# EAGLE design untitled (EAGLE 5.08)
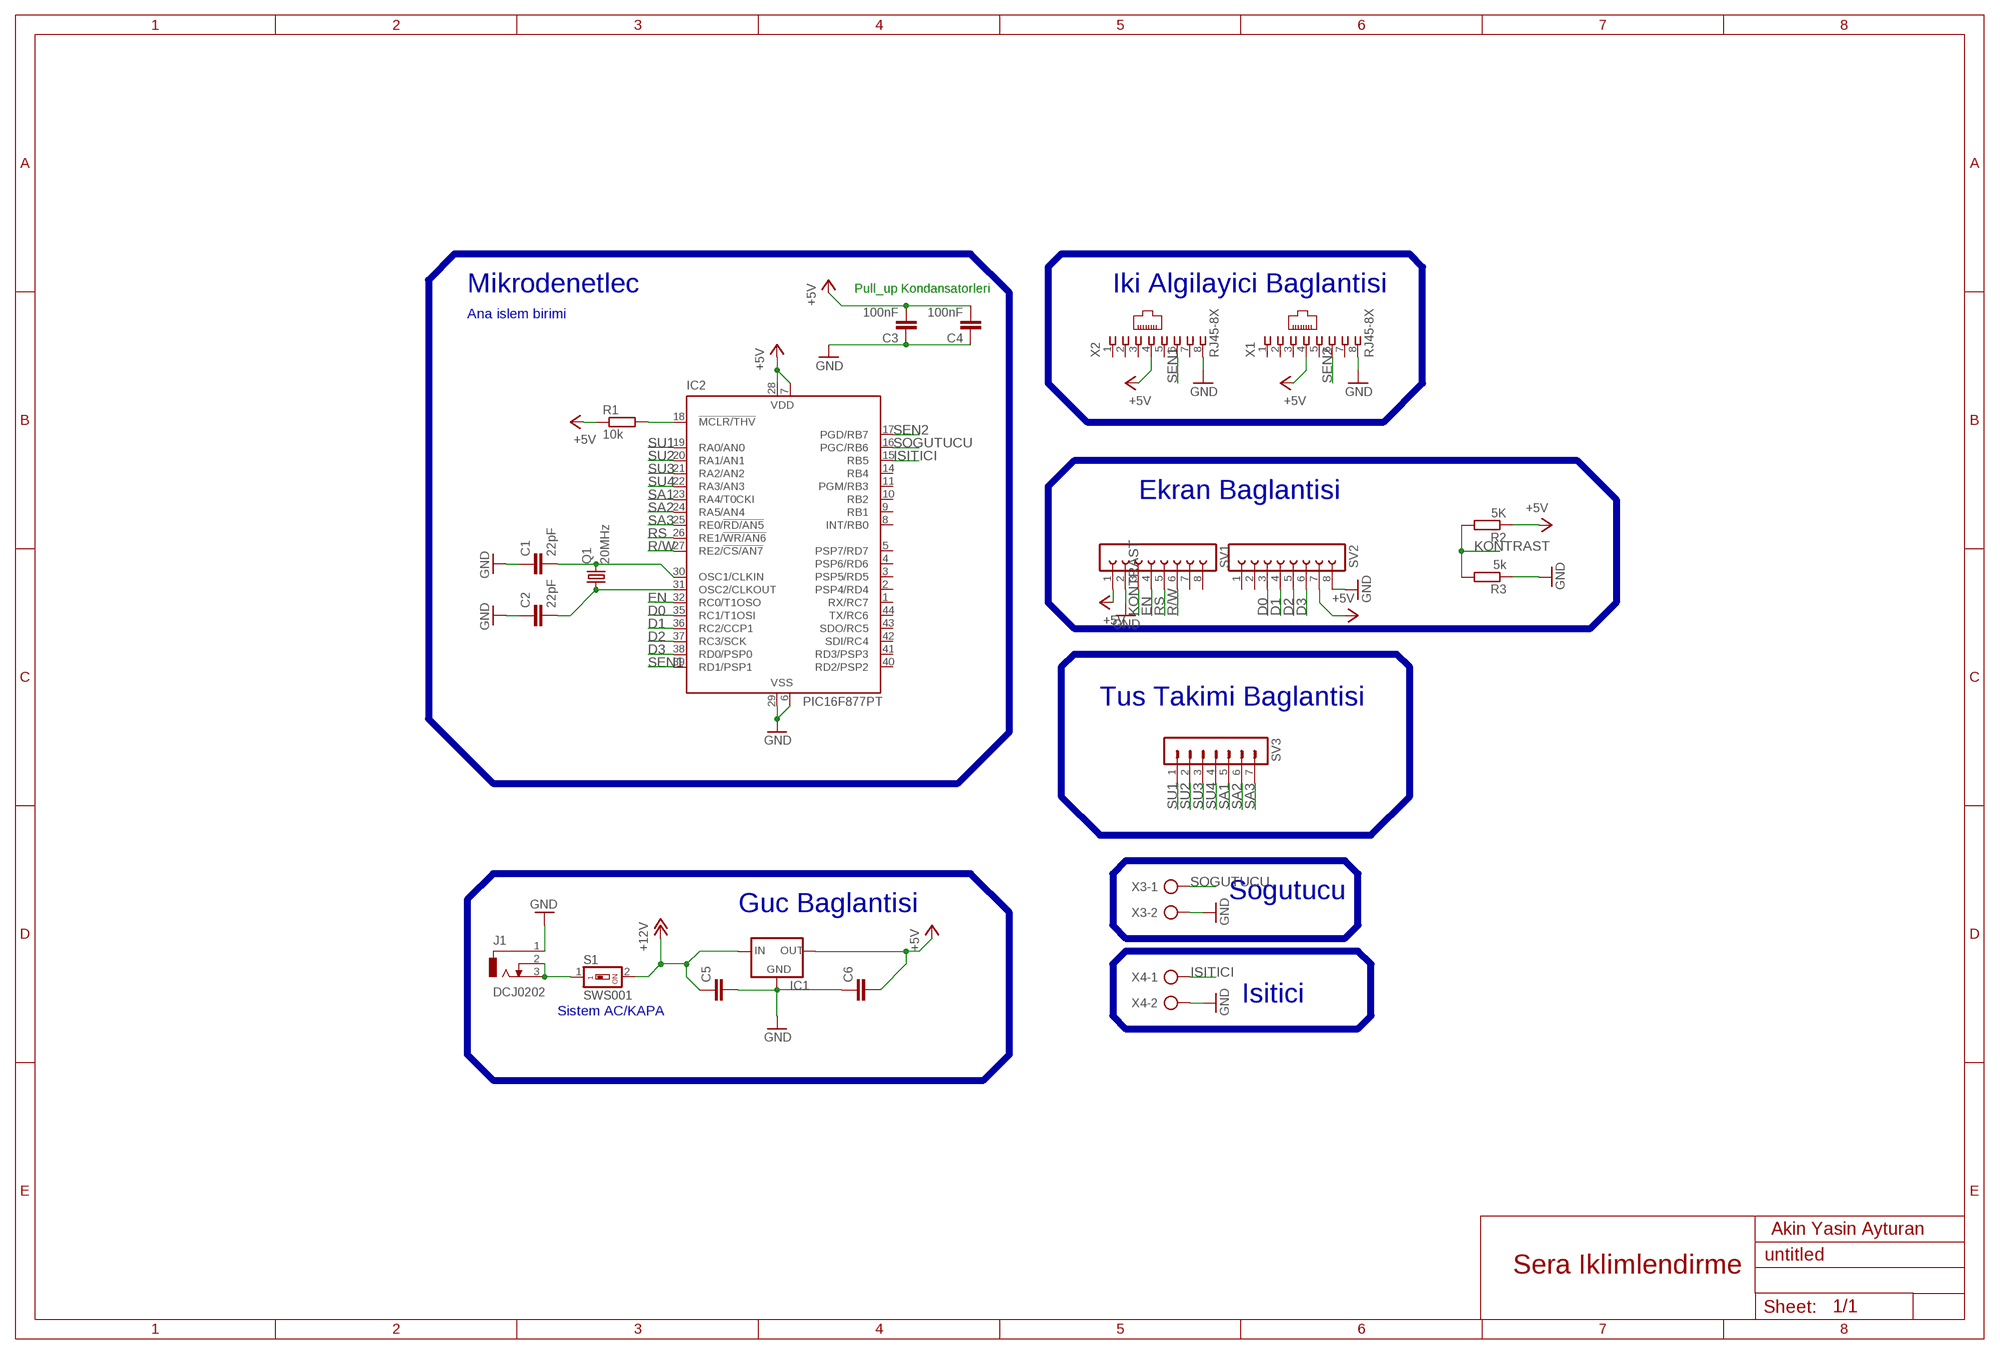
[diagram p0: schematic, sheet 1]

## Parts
C1  22pF  C-EUC0402  [C0402]
C2  22pF  C-EUC0402  [C0402]
C3  100nF  C-EUC1206  [C1206]
C4  100nF  C-EUC1206  [C1206]
C5  C-EU050-045X075  [C050-045X075]
C6  C-EU050-045X075  [C050-045X075]
IC1  78LXX  [78LXX]
IC2  PIC16F877PT  [TQFP44]
J1  DCJ0202  [DCJ0202]
Q1  20MHz  CRYSTALSM49  [SM49]
R1  10k  R-EU_M1206  [M1206]
R2  5K  R-EU_M1206  [M1206]
R3  5k  R-EU_M1206  [M1206]
S1  SWS001  [SMS-001]
SV1  FE08-1  [FE08]
SV2  FE08-1  [FE08]
SV3  MA07-1  [MA07-1]
X1  RJ45-8X  [RJ45-NO-SHIELD]
X2  RJ45-8X  [RJ45-NO-SHIELD]
X3  AK300/2  [AK300/2]
X4  AK300/2  [AK300/2]

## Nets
+5V: C3.2 C4.2 C6.2 IC1.OUT IC2.7(VDD) IC2.28(VDD) R1.1 R2.1 SV1.1 SV2.7 X1.4 X2.4
+12V: C5.1 IC1.IN S1.2
D0: IC2.35(RC1/T1OSI) SV2.3
D1: IC2.36(RC2/CCP1) SV2.4
D2: IC2.37(RC3/SCK) SV2.5
D3: IC2.38(RD0/PSP0) SV2.6
EN: IC2.32(RC0/T1OSO) SV1.4
GND: C1.1 C2.1 C3.1 C4.1 C5.2 C6.1 IC1.GND IC2.6(VSS) IC2.29(VSS) J1.1 R3.1 SV1.2 SV2.8 X1.8 X2.8 X3.2 X4.2
ISITICI: IC2.15(RB5) X4.1
KONTRAST: R2.2 R3.2 SV1.3
N$1: IC2.18(!MCLR/THV) R1.2
N$2: C1.2 IC2.30(OSC1/CLKIN) Q1.2
N$3: C2.2 IC2.31(OSC2/CLKOUT) Q1.1
N$4: J1.2 J1.3 S1.1
R/W: IC2.27(RE2/!CS/AN7) SV1.6
RS: IC2.26(RE1/!WR/AN6) SV1.5
SA1: IC2.23(RA4/T0CKI) SV3.5
SA2: IC2.24(RA5/AN4) SV3.6
SA3: IC2.25(RE0/!RD/AN5) SV3.7
SEN1: IC2.39(RD1/PSP1) X2.6
SEN2: IC2.17(PGD/RB7) X1.6
SOGUTUCU: IC2.16(PGC/RB6) X3.1
SU1: IC2.19(RA0/AN0) SV3.1
SU2: IC2.20(RA1/AN1) SV3.2
SU3: IC2.21(RA2/AN2) SV3.3
SU4: IC2.22(RA3/AN3) SV3.4
Unconnected: IC2.1(RX/RC7) IC2.2(PSP4/RD4) IC2.3(PSP5/RD5) IC2.4(PSP6/RD6) IC2.5(PSP7/RD7) IC2.8(INT/RB0) IC2.9(RB1) IC2.10(RB2) IC2.11(PGM/RB3) IC2.14(RB4) IC2.40(RD2/PSP2) IC2.41(RD3/PSP3) IC2.42(SDI/RC4) IC2.43(SDO/RC5) IC2.44(TX/RC6) SV1.7 SV1.8 SV2.1 SV2.2 X1.1 X1.2 X1.3 X1.5 X1.7 X2.1 X2.2 X2.3 X2.5 X2.7

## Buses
B$2
B$3
B$4
B$5
B$6
B$7
B$1

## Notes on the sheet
- Mikrodenetlec | Pull_up Kondansatorleri | Iki Algilayici Baglantisi
- Ana islem birimi
- Ekran Baglantisi
- Tus Takimi Baglantisi
- Sogutucu
- Guc Baglantisi
- Isitici
- Sistem AC/KAPA
- Akin Yasin Ayturan
- Sera Iklimlendirme

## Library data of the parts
C1-C6 = resistor:C-EU: CAPACITOR, European symbol
IC1 = v-reg:78LXX: VOLTAGE REGULATOR
IC2 = microchip:PIC16F87*: MICROCONTROLLER
J1 = con-jack:DCJ0202: DC POWER JACK Source: DCJ0202.pdf
Q1 = crystal:CRYSTAL: CRYSTAL
R1-R3 = resistor:R-EU_: RESISTOR, European symbol
S1 = smd-special:SWS001: SMD Dip Switch 1 pol.
SV1 SV2 = con-lsta:FE08-1: FEMALE HEADER
SV3 = con-lstb:MA07-1: PIN HEADER
X1 X2 = con-tycoelectronics:RJ45: CORCOM Modular RJ Jacks No Shield Source: www.tycoelectronics.com .. ENG_DS_1654001_1099_RJ_L_0507.pdf
X3 X4 = con-ptr500:AK300/2: CONNECTOR

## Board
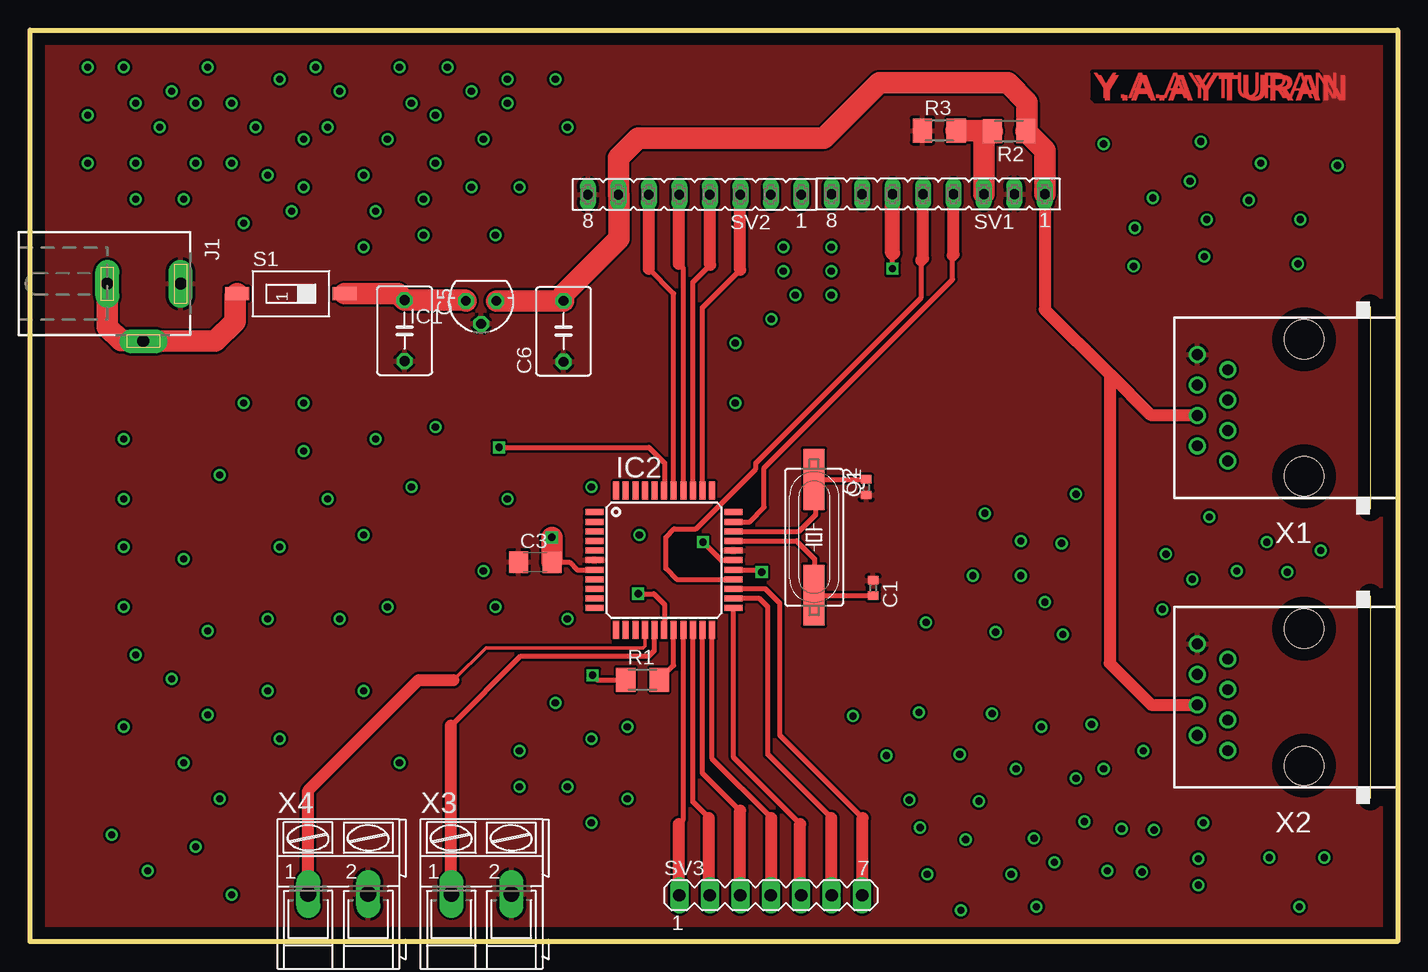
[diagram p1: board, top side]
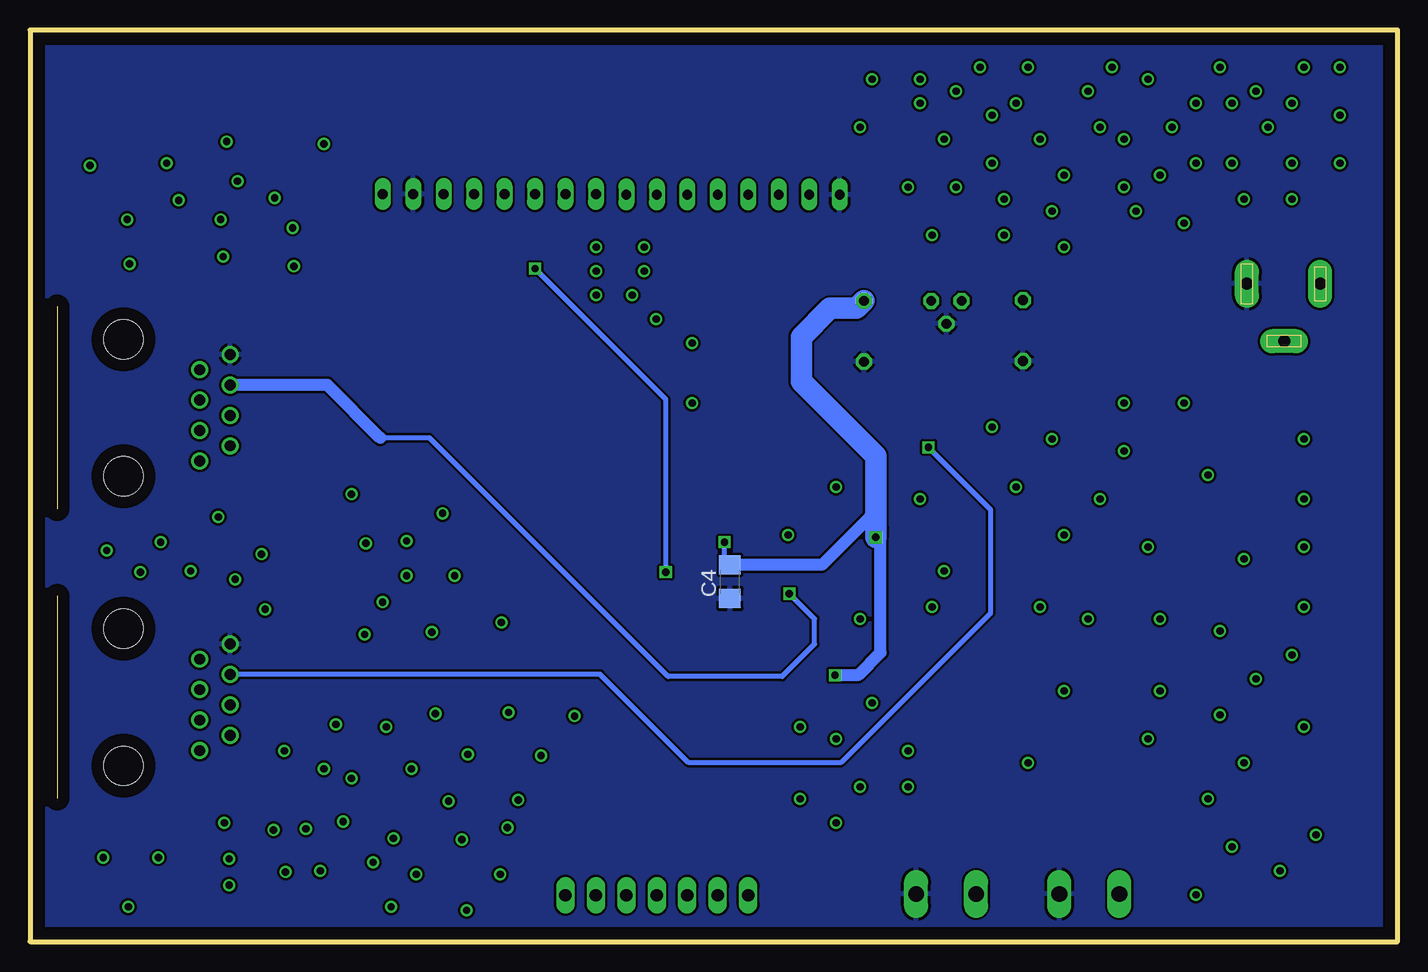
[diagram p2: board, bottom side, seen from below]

Size 114 x 76 mm. Coordinates in mm from the lower left corner, seen from the top.
Outline: 0,0 0,76 114,76 114,0 0,0
Copper layers (1*16): Top 0.035mm / dielectric 1.5mm / Bottom 0.035mm
Design rules "default": minimum track width 10mil, minimum drill 24mil, track to track 8mil, track to pad 8mil, pad to pad 8mil, via to via 8mil, smd to smd 8mil, copper to edge 40mil, drill to drill 8mil, minimum pad ring 10mil, minimum via ring 8mil, stop-mask expansion 4mil, vias tented up to drill 0mil, thermal gap 10mil

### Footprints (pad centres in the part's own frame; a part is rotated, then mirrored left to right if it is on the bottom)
C0402 = smd 0.7 x 0.9: 1 -0.65,0; 2 0.65,0
C1206 = smd 1.6 x 1.8: 1 -1.4,0; 2 1.4,0
C050-045X075 = drill 0.813 octagon: 1 -2.54,0; 2 2.54,0
78LXX = drill 0.813 octagon: GND 0,1.905; IN 1.27,0; OUT -1.27,0
TQFP44 = smd 1.5 x 0.5: 1 -5.8,4; 2 -5.8,3.2; 3 -5.8,2.4; 4 -5.8,1.6; 5 -5.8,0.8; 6 -5.8,0; 7 -5.8,-0.8; 8 -5.8,-1.6; 9 -5.8,-2.4; 10 -5.8,-3.2; 11 -5.8,-4; 23 5.8,-4; 24 5.8,-3.2; 25 5.8,-2.4; 26 5.8,-1.6; 27 5.8,-0.8; 28 5.8,0; 29 5.8,0.8; 30 5.8,1.6; 31 5.8,2.4; 32 5.8,3.2; 33 5.8,4 | smd 0.5 x 1.5: 12 -4,-5.8; 13 -3.2,-5.8; 14 -2.4,-5.8; 15 -1.6,-5.8; 16 -0.8,-5.8; 17 0,-5.8; 18 0.8,-5.8; 19 1.6,-5.8; 20 2.4,-5.8; 21 3.2,-5.8; 22 4,-5.8; 34 4,5.8; 35 3.2,5.8; 36 2.4,5.8; 37 1.6,5.8; 38 0.8,5.8; 39 0,5.8; 40 -0.8,5.8; 41 -1.6,5.8; 42 -2.4,5.8; 43 -3.2,5.8; 44 -4,5.8
DCJ0202 = drill 1 pad 2 long: 1 0,3.1; 2 4.8,0; 3 0,-3
SM49 = smd 5.08 x 1.778: 1 -4.826,0; 2 4.826,0
M1206 = smd 1.6 x 2: 1 -1.4,0; 2 1.4,0
SMS-001 = smd 1.092 x 2.007: 1 0,-4.496; 2 0,4.496
FE08 = drill 0.813 long: 1 -8.89,0; 2 -6.35,0; 3 -3.81,0; 4 -1.27,0; 5 1.27,0; 6 3.81,0; 7 6.35,0; 8 8.89,0
MA07-1 = drill 1.016 long: 1 -7.62,0; 2 -5.08,0; 3 -2.54,0; 4 0,0; 5 2.54,0; 6 5.08,0; 7 7.62,0
RJ45-NO-SHIELD = drill 0.9 pad 1.4 round: 1 -4.445,6.35; 2 -3.175,8.89; 3 -1.905,6.35; 4 -0.635,8.89; 5 0.635,6.35; 6 1.905,8.89; 7 3.175,6.35; 8 4.445,8.89 | hole 3.251: -5.715,0; 5.715,0
AK300/2 = drill 1.321 long: 1 -2.515,0; 2 2.489,0

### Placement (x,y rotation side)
C1  70.29,29.47 270 top
C2  69.71,37.88 90 top
C3  42.12,31.64 0 top
C4  55.66,30 90 bottom
C5  31.22,50.93 270 top
C6  44.48,50.88 90 top
IC1  37.61,53.41 180 top
IC2  52.86,31.8 0 top
J1  9.45,54.85 270 top
Q1  65.36,33.7 270 top
R1  51.06,21.82 0 top
R2  81.62,67.58 180 top
R3  75.8,67.62 0 top
S1  21.75,54.01 270 top
SV1  75.71,62.32 180 top
SV2  55.4,62.28 180 top
SV3  61.75,3.86 0 top
X1  106.2,44.5 90 top
X2  106.2,20.37 90 top
X3  37.64,3.96 0 top
X4  25.71,3.96 0 top

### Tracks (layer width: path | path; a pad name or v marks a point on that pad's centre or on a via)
+5V  (via drill 0.6)
  Top 0.406: C3.2 44.96,31.64 45.6,31 IC2.7 | R1.1 47.28,21.82 v46.9,22.2 | IC2.28 57.6,31.8 v56.1,33.3
  Top 1.016: SV1.1 84.6,52.7 90,47.3 | 90,47.3 93.4,43.9 97.28,43.9 X1.4 | X2.4 93.47,19.73 90,23.2 90,47.3
  Top 1.778: IC1.OUT C6.2 44.48,53.98 49.1,58.6 49.1,62.23 SV2.7 49.05,65.35 50.7,67 66.2,67 70.8,71.6 81.5,71.6 83.1,70 83.1,67.66 R2.1 84.6,66 SV1.1 | C3.2 43.52,33.68 v43.5,33.7
  Bottom 0.406: v56.1,33.3 56.1,31.84 C4.2
  Bottom 1.016: v46.9,22.2 45,22.2 43.1,24.1 43.1,34.2 43.5,34.6 | C4.2 48,31.4 44,35.4 43.6,35.4 43.5,35.5
  Bottom 1.778: v43.5,33.7 43.5,34.6 43.5,35.5 43.5,40.5 49.7,46.7 49.7,50.4 47.3,52.8 45.1,52.8 C6.2
+12V
  Top 1.778: S1.2 30.68,54.01 C5.1 36.28,53.47 IC1.IN
D0
  Top 0.406: IC2.35 56.06,52.86 59.2,56
  Top 1.016: 59.2,56 SV2.3
D1
  Top 0.406: IC2.36 55.26,54.96 56.7,56.4
  Top 1.016: 56.7,56.4 56.7,62.25 SV2.4
D2
  Top 0.406: IC2.37 54.46,56.14 54.1,56.5
  Top 1.016: 54.1,56.5 54.1,62.25 SV2.5
D3
  Top 0.406: IC2.38 53.66,54.04 51.6,56.1
  Top 1.016: 51.6,56.1 SV2.6
EN
  Top 0.406: 76.9,57.2 76.9,55.2 61.2,39.5 61.2,36.2 60,35 IC2.32
  Top 1.016: SV1.4 76.98,57.28 76.9,57.2
GND
  pour Top: 0.8,61.9 0.8,0.9 112.8,0.9 112.8,74.9 0.8,74.9
  pour Bottom: 0.8,74.9 0.8,0.9 112.8,0.9 112.8,74.9
ISITICI
  Top 0.305: IC2.15 51.26,24.66 51.1,24.5 38,24.5 35.3,21.8
  Top 1.016: 35.3,21.8 32.4,21.8 23.2,12.6 X4.1
KONTRAST
  Top 1.778: SV1.3 79.52,66.88 R2.2 80.18,67.62 R3.2
N$1
  Top 0.406: IC2.18 53.66,23.02 R1.2
N$2
  Top 0.406: IC2.30 63.9,33.4 65.4,31.9 65.4,28.91 Q1.2 70.24,28.87 C1.2
N$3
  Top 0.406: IC2.31 64.1,34.2 65.5,35.6 65.5,38.39 Q1.1 C2.2
N$4
  Top 1.778: J1.3 6.45,51.25 7.6,50.1 9.4,50.1 J1.2 15.45,50.05 17.1,51.7 17.1,53.86 S1.1
N$5  (via drill 0.6)
  other vias: 7.8,41.9
N$6  (via drill 0.6)
  other vias: 7.8,36.9
N$7  (via drill 0.6)
  other vias: 7.8,32.9
N$8  (via drill 0.6)
  other vias: 7.8,27.9
N$9  (via drill 0.6)
  other vias: 8.8,23.9
N$10  (via drill 0.6)
  other vias: 7.8,17.9
N$11  (via drill 0.6)
  other vias: 6.8,8.9
N$12  (via drill 0.6)
  other vias: 12.8,14.9
N$13  (via drill 0.6)
  other vias: 11.8,21.9
N$14  (via drill 0.6)
  other vias: 19.8,26.9
N$15  (via drill 0.6)
  other vias: 12.8,31.9
N$16  (via drill 0.6)
  other vias: 15.8,38.9
N$17  (via drill 0.6)
  other vias: 24.8,36.9
N$18  (via drill 0.6)
  other vias: 20.8,32.9
N$19  (via drill 0.6)
  other vias: 25.8,26.9
N$20  (via drill 0.6)
  other vias: 19.8,20.9
N$21  (via drill 0.6)
  other vias: 27.8,20.9
N$22  (via drill 0.6)
  other vias: 14.8,25.9
N$23  (via drill 0.6)
  other vias: 22.8,44.9
N$24  (via drill 0.6)
  other vias: 17.8,44.9
N$25  (via drill 0.6)
  other vias: 22.8,40.9
N$26  (via drill 0.6)
  other vias: 33.8,42.9
N$27  (via drill 0.6)
  other vias: 28.8,41.9
N$28  (via drill 0.6)
  other vias: 27.8,33.9
N$29  (via drill 0.6)
  other vias: 29.8,27.9
N$30  (via drill 0.6)
  other vias: 31.8,37.9
N$31  (via drill 0.6)
  other vias: 39.8,36.9
N$32  (via drill 0.6)
  other vias: 37.8,30.9
N$33  (via drill 0.6)
  other vias: 38.8,27.9
N$34  (via drill 0.6)
  other vias: 46.8,37.9
N$35  (via drill 0.6)
  other vias: 44.8,26.9
N$36  (via drill 0.6)
  other vias: 50.8,33.9
N$37  (via drill 0.6)
  other vias: 43.8,19.9
N$38  (via drill 0.6)
  other vias: 49.8,17.9
N$39  (via drill 0.6)
  other vias: 46.8,16.9
N$40  (via drill 0.6)
  other vias: 40.8,15.9
N$41  (via drill 0.6)
  other vias: 49.8,11.9
N$42  (via drill 0.6)
  other vias: 40.8,12.9
N$43  (via drill 0.6)
  other vias: 46.8,9.9
N$44  (via drill 0.6)
  other vias: 44.8,12.9
N$45  (via drill 0.6)
  other vias: 30.8,14.9
N$46  (via drill 0.6)
  other vias: 15.8,11.9
N$47  (via drill 0.6)
  other vias: 13.8,7.9
N$48  (via drill 0.6)
  other vias: 16.8,3.9
N$49  (via drill 0.6)
  other vias: 9.8,5.9
N$50  (via drill 0.6)
  other vias: 20.8,16.9
N$51  (via drill 0.6)
  other vias: 14.8,18.9
N$52  (via drill 0.6)
  other vias: 4.8,72.9
N$53  (via drill 0.6)
  other vias: 4.8,68.9
N$54  (via drill 0.6)
  other vias: 4.8,64.9
N$55  (via drill 0.6)
  other vias: 8.8,64.9
N$56  (via drill 0.6)
  other vias: 10.8,67.9
N$57  (via drill 0.6)
  other vias: 11.8,70.9
N$58  (via drill 0.6)
  other vias: 7.8,72.9
N$59  (via drill 0.6)
  other vias: 8.8,69.9
N$60  (via drill 0.6)
  other vias: 20.8,71.9
N$61  (via drill 0.6)
  other vias: 18.8,67.9
N$62  (via drill 0.6)
  other vias: 16.8,69.9
N$63  (via drill 0.6)
  other vias: 14.8,72.9
N$64  (via drill 0.6)
  other vias: 16.8,64.9
N$65  (via drill 0.6)
  other vias: 13.8,64.9
N$66  (via drill 0.6)
  other vias: 13.8,69.9
N$67  (via drill 0.6)
  other vias: 22.8,62.9
N$68  (via drill 0.6)
  other vias: 17.8,59.9
N$69  (via drill 0.6)
  other vias: 12.8,61.9
N$70  (via drill 0.6)
  other vias: 8.8,61.9
N$71  (via drill 0.6)
  other vias: 21.8,60.9
N$72  (via drill 0.6)
  other vias: 27.8,57.9
N$73  (via drill 0.6)
  other vias: 19.8,63.9
N$74  (via drill 0.6)
  other vias: 24.8,67.9
N$75  (via drill 0.6)
  other vias: 22.8,66.9
N$76  (via drill 0.6)
  other vias: 25.8,70.9
N$77  (via drill 0.6)
  other vias: 31.8,69.9
N$78  (via drill 0.6)
  other vias: 29.8,66.9
N$79  (via drill 0.6)
  other vias: 27.8,63.9
N$80  (via drill 0.6)
  other vias: 32.8,61.9
N$81  (via drill 0.6)
  other vias: 32.8,58.9
N$82  (via drill 0.6)
  other vias: 38.8,58.9
N$83  (via drill 0.6)
  other vias: 28.8,60.9
N$84  (via drill 0.6)
  other vias: 33.8,64.9
N$85  (via drill 0.6)
  other vias: 40.8,62.9
N$86  (via drill 0.6)
  other vias: 36.8,62.9
N$87  (via drill 0.6)
  other vias: 37.8,66.9
N$88  (via drill 0.6)
  other vias: 33.8,68.9
N$89  (via drill 0.6)
  other vias: 44.8,67.9
N$90  (via drill 0.6)
  other vias: 39.8,69.9
N$91  (via drill 0.6)
  other vias: 36.8,70.9
N$92  (via drill 0.6)
  other vias: 43.8,71.9
N$93  (via drill 0.6)
  other vias: 39.8,71.9
N$94  (via drill 0.6)
  other vias: 34.8,72.9
N$95  (via drill 0.6)
  other vias: 30.8,72.9
N$96  (via drill 0.6)
  other vias: 23.8,72.9
N$97  (via drill 0.6)
  other vias: 62.8,57.9
N$98  (via drill 0.6)
  other vias: 66.8,57.9
N$99  (via drill 0.6)
  other vias: 62.8,55.9
N$100  (via drill 0.6)
  other vias: 61.8,51.9
N$101  (via drill 0.6)
  other vias: 58.8,49.9
N$102  (via drill 0.6)
  other vias: 58.8,44.9
N$103  (via drill 0.6)
  other vias: 66.8,53.9
N$104  (via drill 0.6)
  other vias: 63.8,53.9
N$105  (via drill 0.6)
  other vias: 66.8,55.9
N$106  (via drill 0.6)
  other vias: 68.6,18.8
N$107  (via drill 0.6)
  other vias: 71.4,15.5
N$108  (via drill 0.6)
  other vias: 73.3,11.8
N$109  (via drill 0.6)
  other vias: 74.8,5.6
N$110  (via drill 0.6)
  other vias: 74.2,9.5
N$111  (via drill 0.6)
  other vias: 81.8,5.6
N$112  (via drill 0.6)
  other vias: 79.1,11.7
N$113  (via drill 0.6)
  other vias: 78,8.5
N$114  (via drill 0.6)
  other vias: 77.5,15.6
N$115  (via drill 0.6)
  other vias: 84.3,17.9
N$116  (via drill 0.6)
  other vias: 74.1,19.1
N$117  (via drill 0.6)
  other vias: 82.2,14.4
N$118  (via drill 0.6)
  other vias: 87.9,10
N$119  (via drill 0.6)
  other vias: 83.7,8.6
N$120  (via drill 0.6)
  other vias: 89.5,14.4
N$121  (via drill 0.6)
  other vias: 80.2,19
N$122  (via drill 0.6)
  other vias: 88.5,18.1
N$123  (via drill 0.6)
  other vias: 92.8,15.9
N$124  (via drill 0.6)
  other vias: 93.7,9.3
N$125  (via drill 0.6)
  other vias: 87.2,13.6
N$126  (via drill 0.6)
  other vias: 85.4,6.6
N$127  (via drill 0.6)
  other vias: 92.7,5.8
N$128  (via drill 0.6)
  other vias: 89.8,5.9
N$129  (via drill 0.6)
  other vias: 91,9.4
N$130  (via drill 0.6)
  other vias: 97.8,9.9
N$131  (via drill 0.6)
  other vias: 97.4,4.7
N$132  (via drill 0.6)
  other vias: 97.4,6.9
N$133  (via drill 0.6)
  other vias: 105.8,2.9
N$134  (via drill 0.6)
  other vias: 107.9,7
N$135  (via drill 0.6)
  other vias: 103.3,7
N$136  (via drill 0.6)
  other vias: 83.9,2.9
N$137  (via drill 0.6)
  other vias: 77.6,2.6
N$138  (via drill 0.6)
  other vias: 74.7,26.6
N$139  (via drill 0.6)
  other vias: 79.6,35.7
N$140  (via drill 0.6)
  other vias: 78.6,30.5
N$141  (via drill 0.6)
  other vias: 84.6,28.3
N$142  (via drill 0.6)
  other vias: 82.6,33.4
N$143  (via drill 0.6)
  other vias: 87.2,37.3
N$144  (via drill 0.6)
  other vias: 82.6,30.5
N$145  (via drill 0.6)
  other vias: 80.5,25.8
N$146  (via drill 0.6)
  other vias: 86,33.2
N$147  (via drill 0.6)
  other vias: 86.1,25.6
N$148  (via drill 0.6)
  other vias: 98.3,35.4
N$149  (via drill 0.6)
  other vias: 96.9,30.2
N$150  (via drill 0.6)
  other vias: 94.4,27.7
N$151  (via drill 0.6)
  other vias: 94.7,32.3
N$152  (via drill 0.6)
  other vias: 100.6,30.9
N$153  (via drill 0.6)
  other vias: 107.6,32.6
N$154  (via drill 0.6)
  other vias: 103.1,33.3
N$155  (via drill 0.6)
  other vias: 104.8,30.8
N$156  (via drill 0.6)
  other vias: 93.6,62
N$157  (via drill 0.6)
  other vias: 92.1,59.5
N$158  (via drill 0.6)
  other vias: 92,56.3
N$159  (via drill 0.6)
  other vias: 97.9,57.1
N$160  (via drill 0.6)
  other vias: 105.9,60.2
N$161  (via drill 0.6)
  other vias: 109,64.7
N$162  (via drill 0.6)
  other vias: 102.6,64.9
N$163  (via drill 0.6)
  other vias: 101.6,61.8
N$164  (via drill 0.6)
  other vias: 96.7,63.4
N$165  (via drill 0.6)
  other vias: 97.6,66.7
N$166  (via drill 0.6)
  other vias: 98.1,60.2
N$167  (via drill 0.6)
  other vias: 105.7,56.5
N$168  (via drill 0.6)
  other vias: 89.5,66.5
R/W  (via drill 0.6)
  Top 0.406: IC2.27 60.8,31 v61,30.8 | v71.9,56.1 71.9,57.4
  Top 1.27: 71.9,57.4 SV1.6
  Bottom 0.406: v61,30.8 61,45.2 v71.9,56.1
RS
  Top 0.406: 74.3,56.8 74.3,53.7 60.5,39.9 60.5,39.4 55.5,34.4 53.7,34.4 53,33.7 53,31.1 53.9,30.2 IC2.26
  Top 1.016: SV1.5 74.44,56.94 74.3,56.8
SA1
  Top 0.406: IC2.23 58.66,15.34 64.2,9.8
  Top 1.016: 64.2,9.8 64.2,3.95 SV3.5
SA2
  Top 0.406: IC2.24 60.8,28.6 61.5,27.9 61.5,15.6 66.8,10.3
  Top 1.016: 66.8,10.3 66.8,3.89 SV3.6
SA3
  Top 0.406: IC2.25 61.3,29.4 62.5,28.2 62.5,17.2 69.4,10.3
  Top 1.016: 69.4,10.3 69.4,3.89 SV3.7
SEN1  (via drill 0.6)
  Top 0.406: v39.1,41.2 51.6,41.2 52.9,39.9 52.9,37.64 IC2.39
  Bottom 0.406: X2.6 66.47,22.27 59.1,14.9 46.4,14.9 33.9,27.4 33.9,36 v39.1,41.2
SEN2  (via drill 0.6)
  Top 0.406: v50.7,29 52,29 52.9,28.1 52.9,26.04 IC2.17
  Bottom 0.406: 84.8,42 80.7,42 60.8,22.1 51.3,22.1 48.6,24.8 48.6,26.9 v50.7,29
  Bottom 1.016: X1.6 89.2,46.41 84.8,42
SOGUTUCU
  Top 0.406: IC2.16 52.06,24.26 51.6,23.8 40.9,23.8 35.1,18
  Top 1.016: 35.1,18 35.1,3.98 X3.1
SU1
  Top 0.406: IC2.19 54.46,10.16 54.1,9.8
  Top 1.016: 54.1,9.8 54.1,3.89 SV3.1
SU2
  Top 0.406: IC2.20 55.26,11.64 56.6,10.3
  Top 1.016: 56.6,10.3 56.6,3.93 SV3.2
SU3
  Top 0.406: IC2.21 56.06,14.04 59.2,10.9
  Top 1.016: 59.2,10.9 SV3.3
SU4
  Top 0.406: IC2.22 56.86,15.24 61.8,10.3
  Top 1.016: 61.8,10.3 61.8,3.91 SV3.4

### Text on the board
Top: Y.A.AYTURAN | Y.A.AYTURAN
